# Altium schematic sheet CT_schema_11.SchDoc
size 519 x 434 mm
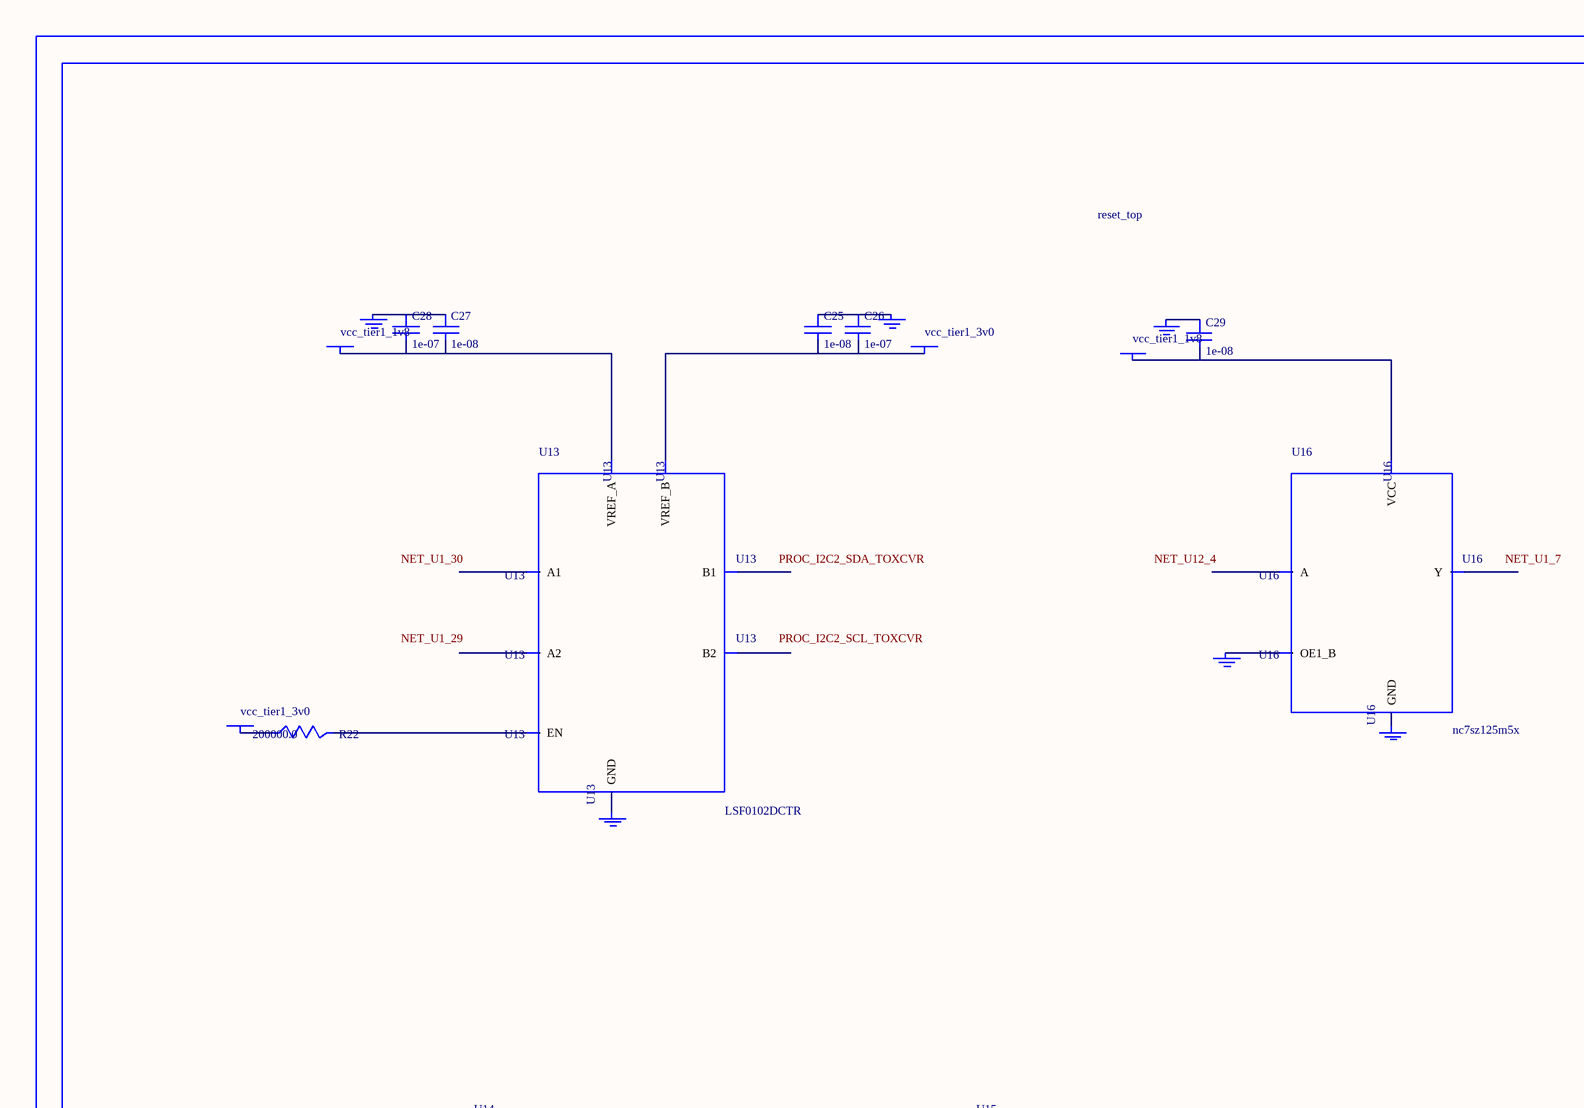
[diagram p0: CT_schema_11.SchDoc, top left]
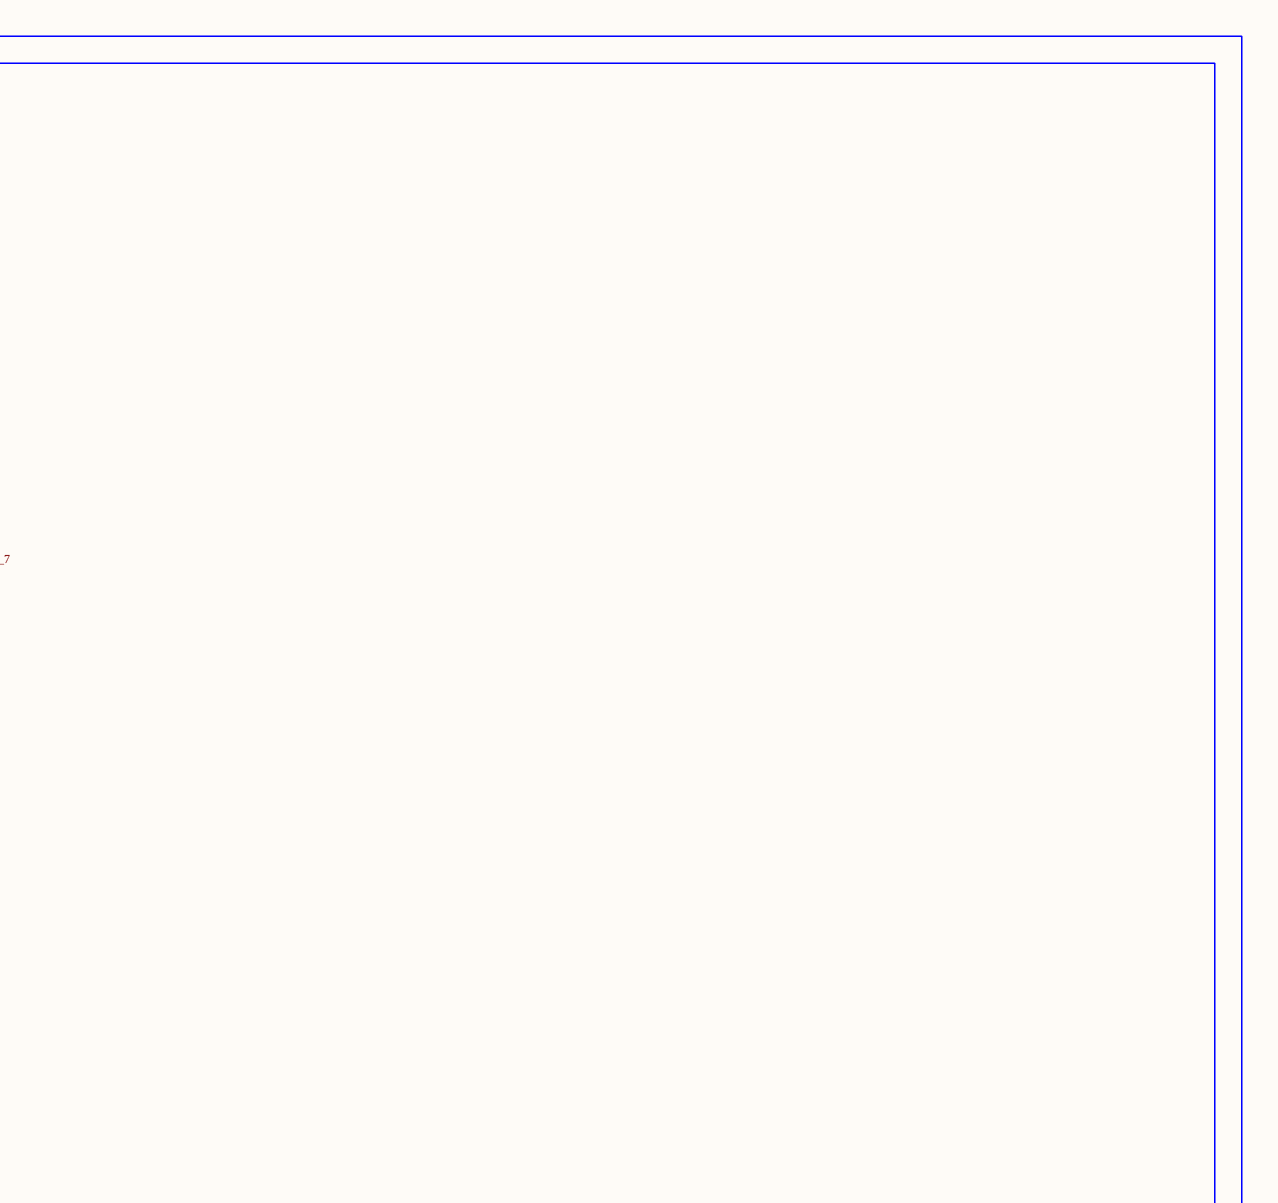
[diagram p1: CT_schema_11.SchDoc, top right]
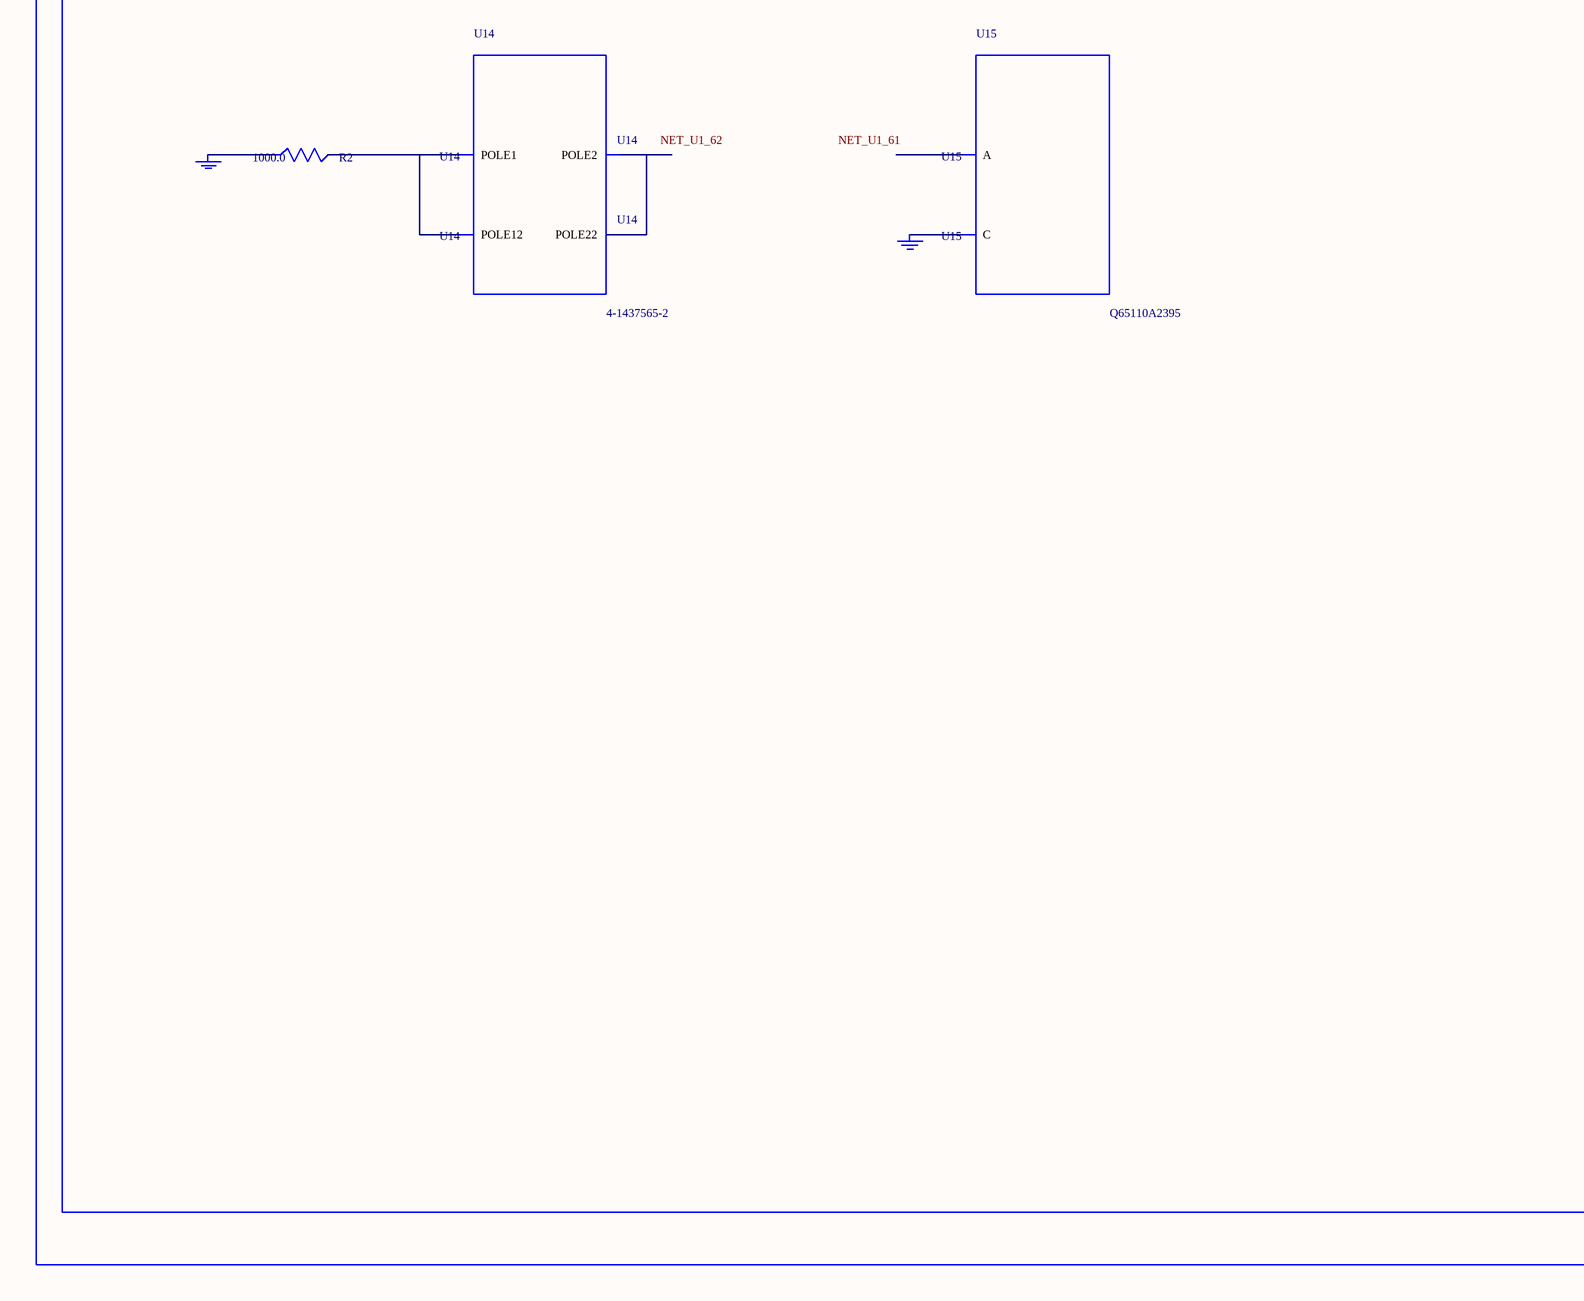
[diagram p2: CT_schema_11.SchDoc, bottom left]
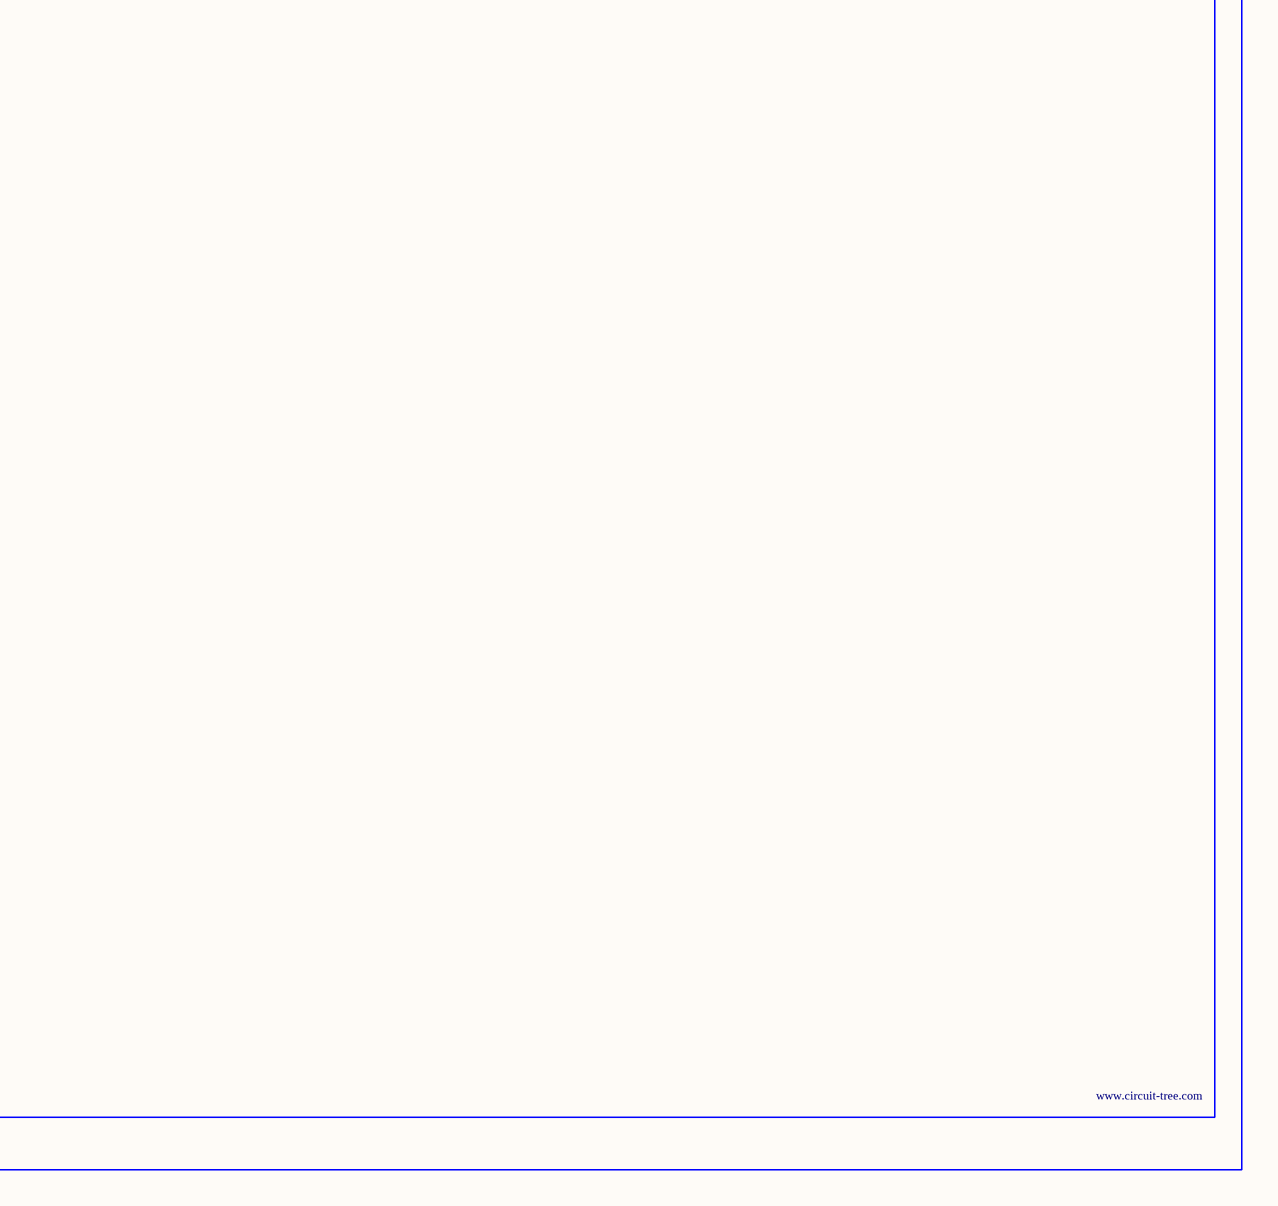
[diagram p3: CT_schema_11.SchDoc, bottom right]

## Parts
BORDER10  (no value)
C25  1e-08  [C0402]
C26  1e-07  [C0402]
C27  1e-08  [C0402]
C28  1e-07  [C0402]
C29  1e-08  [C0402]
GND_INSTANCE_10_0  (no value)
GND_INSTANCE_10_1  (no value)
GND_INSTANCE_10_2  (no value)
GND_INSTANCE_10_3  (no value)
GND_INSTANCE_10_4  (no value)
GND_INSTANCE_10_5  (no value)
GND_INSTANCE_10_6  (no value)
GND_INSTANCE_10_7  (no value)
POWER_INSTANCE_10_0  vcc_tier1_1v8
POWER_INSTANCE_10_1  vcc_tier1_3v0
POWER_INSTANCE_10_2  vcc_tier1_3v0
POWER_INSTANCE_10_3  vcc_tier1_1v8
R2  1000.0  [R0603]
R22  200000.0  [R0603]
U13  LSF0102DCTR  [DCU0008A_N]
U14  4-1437565-2  [SW_4-1437565-2]
U15  Q65110A2395  [LGM67K-G1J2-24-Z]
U16  nc7sz125m5x  [NC7SZ125M5X]

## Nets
NetC25_1: C25.1 C26.1 GND_INSTANCE_10_1.0(GND)
NetC25_2: C25.2 C26.2 POWER_INSTANCE_10_1.0(PWR) U13.7(VREF_B)
NetC27_1: C27.1 C28.1 GND_INSTANCE_10_0.0(GND)
NetC27_2: C27.2 C28.2 POWER_INSTANCE_10_0.0(PWR) U13.2(VREF_A)
NetC29_1: C29.1 GND_INSTANCE_10_5.0(GND)
NetC29_2: C29.2 POWER_INSTANCE_10_3.0(PWR) U16.5(VCC)
NetGND_INSTANCE_10_2_0: GND_INSTANCE_10_2.0(GND) U13.1(GND)
NetGND_INSTANCE_10_3_0: GND_INSTANCE_10_3.0(GND) R2.1
NetGND_INSTANCE_10_4_0: GND_INSTANCE_10_4.0(GND) U15.C
NetGND_INSTANCE_10_6_0: GND_INSTANCE_10_6.0(GND) U16.1(OE1_B)
NetGND_INSTANCE_10_7_0: GND_INSTANCE_10_7.0(GND) U16.3(GND)
NetPOWER_INSTANCE_10_2_0: POWER_INSTANCE_10_2.0(PWR) R22.1
NetR2_2: R2.2 U14.1(POLE1) U14.2(POLE12)
NetR22_2: R22.2 U13.8(EN)
NetU14_3: U14.3(POLE2) U14.4(POLE22)

Not connected (* = marked no-connect by the designer): U13 3(A1) 4(A2) 5(B2) 6(B1); U15 A; U16 2(A) 4(Y)

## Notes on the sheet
- Labels drawn without touching a wire or pin: NET_U1_7, NET_U1_29, NET_U1_30, NET_U1_61, NET_U1_62, NET_U12_4, PROC_I2C2_SCL_TOXCVR, PROC_I2C2_SDA_TOXCVR

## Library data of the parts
BORDER10 = BORDER_PAGE10
C25 C27 C29 = C0402C103K3RAC
C26 C28 = C0402C104K3RACTU
GND_INSTANCE_10_0-GND_INSTANCE_10_7 = GND
POWER_INSTANCE_10_0-POWER_INSTANCE_10_3 = PWR
R2 = RC0603JR-071KL
R22 = RC0603JR-07200KL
